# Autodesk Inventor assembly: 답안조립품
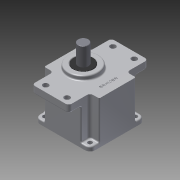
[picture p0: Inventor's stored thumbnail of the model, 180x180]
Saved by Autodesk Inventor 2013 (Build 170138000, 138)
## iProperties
Created: 2015-07
Part Number: 답안조립품
Document SubType Name: Assembly
Designer: user
Author: user
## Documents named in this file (12)
- C:\Users\user\Desktop\450734V1024\답안조립품.iam
- C:\Users\user\Desktop\450734V1024\서브축.ipt
- C:\Users\user\Desktop\450734V1024\베어링 608.ipt
- 베어링 608.ipt
- C:\Users\user\Desktop\450734V1024\베어링 6003.ipt
- 베어링 6003.ipt
- C:\Users\user\Desktop\450734V1024\본체.ipt
- C:\Users\user\Desktop\450734V1024\메인축.ipt
- C:\Users\user\Desktop\450734V1024\커버.ipt
- C:\Users\user\Desktop\450734V1024\오일실 8x22x7.ipt
- C:\Users\user\Desktop\450734V1024\오일실 17x32x8.ipt
- C:\Users\user\Desktop\450734V1024\M4x0.5x16.ipt
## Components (4 placed, 1 different names)
1. M4x0.5x12:1
2. M4x0.5x12:2
3. M4x0.5x12:3
4. M4x0.5x12:4
